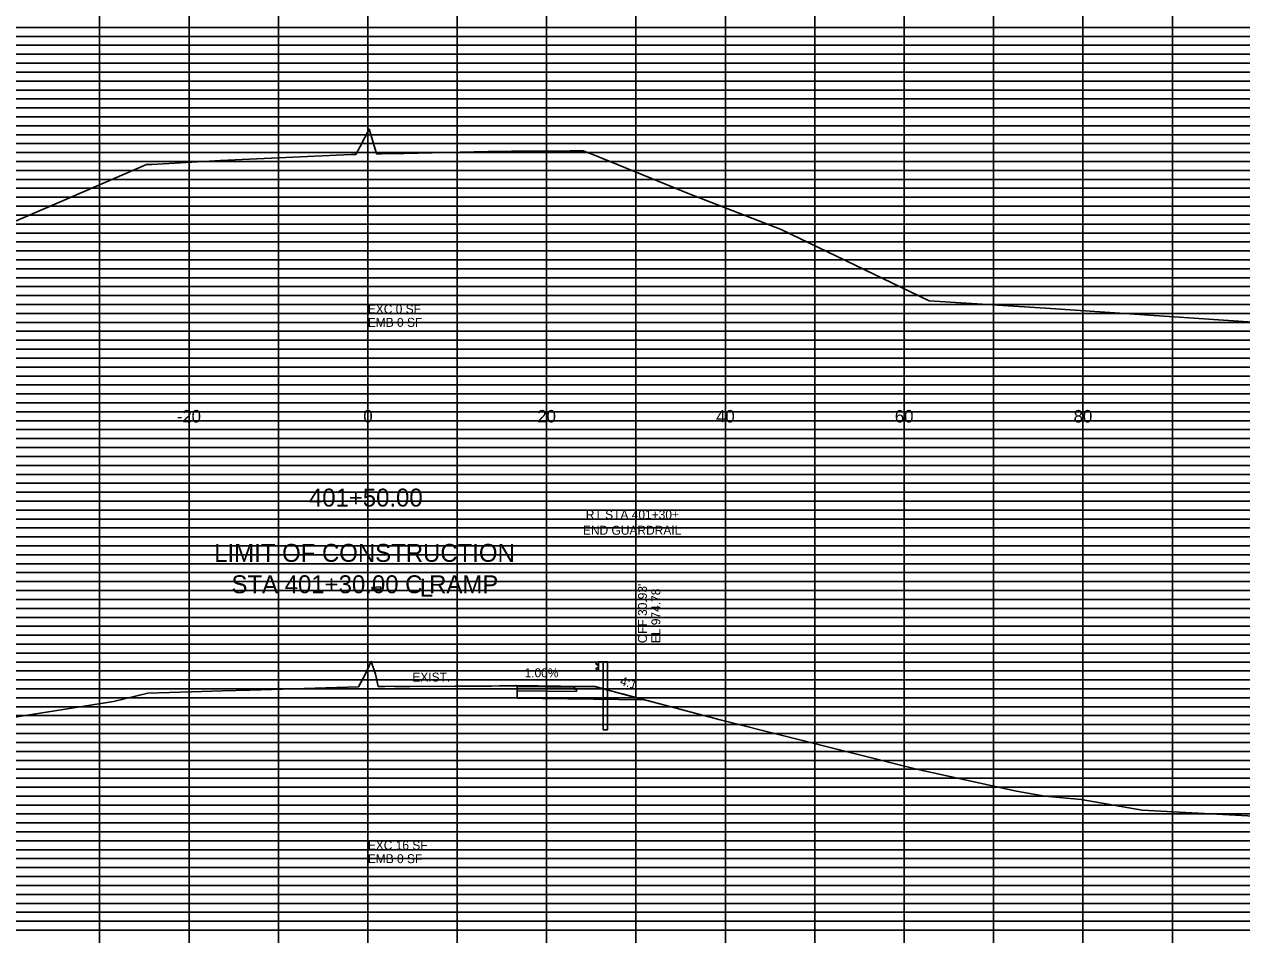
# Model space of a CAD drawing. Extents: x 2313580 to 2322968, y 282099 to 303247.
# Drawn here: x 2315420.5 to 2315556.6, y 285194.6 to 285296.5 of the extents above; entities that cross this region are included whole.
import ezdxf

# ---------------------------------------------------------------- set-up
doc = ezdxf.new("R2010")
doc.units = 0
for name, color, linetype in [('DESIGN - CENTERLINE - Proposed', 7, 'Continuous'), ('DESIGN - DRAINAGE - Text', 7, 'Continuous'), ('DESIGN - EARTHWORK - Excavation Limit Lines', 7, 'Continuous'), ('DESIGN - ROW - Right-of-Way Linework', 7, 'Continuous'), ('DESIGN - SCRATCH - User 1', 7, 'Continuous'), ('DESIGN - SHEET - Light Grid', 7, 'Continuous'), ('DESIGN - SHEET - Linework', 7, 'Continuous'), ('DESIGN - TRANSPORTATION - Text', 7, 'Continuous'), ('DESIGN - TYPICAL - Finished Grade and Subgrade', 7, 'Continuous'), ('DESIGN - TYPICAL - Finished Grade Slopes Text', 7, 'Continuous'), ('DESIGN - TYPICAL - Guardrail', 7, 'Continuous'), ('DESIGN - TYPICAL - Text', 7, 'Continuous'), ('Scratch Level', 7, 'Continuous'), ('SURVEY - GROUND - Top of Ground', 7, 'Continuous')]:
    doc.layers.add(name, color=color, linetype=linetype)

# ---------------------------------------------------------------- blocks, each defined once
blk = doc.blocks.new('GRTYP')
at = {"layer": 'DESIGN - CENTERLINE - Proposed'}
for p, q in [((0.162, 0.37), (0.162, 0.37)), ((0.162, 0.37), (0.162, 0.37)), ((0.264, 0.37), (0.264, 0.37)), ((0.264, 0.37), (0.264, 0.37))]:
    blk.add_line(p, q, dxfattribs=at)
for points in [[(0.059, 0.567), (0.04, 0.563), (0.004, 0.539), (0, 0.531), (0.004, 0.523), (0.055, 0.492), (0.059, 0.484), (0.059, 0.464), (0.055, 0.456), (0.004, 0.425), (0, 0.417), (0.004, 0.409), (0.04, 0.385), (0.059, 0.382)], [(0.162, 0.374), (0.059, 0.374), (0.059, 0.574), (0.162, 0.574)], [(0.264, -0.126), (0.264, 0.574), (0.162, 0.574), (0.162, -0.075)], [(0.162, -0.075), (0.162, -0.949), (0.264, -0.949), (0.264, -0.122)]]:
    blk.add_lwpolyline(points, dxfattribs=at)

msp = doc.modelspace()

# ---------------------------------------------------------------- linework, layer by layer
at = {"layer": 'DESIGN - ROW - Right-of-Way Linework'}
msp.add_lwpolyline([(2315461.92, 285222.39), (2315463.25, 285222.39), (2315463.6, 285222.4), (2315473.62, 285222.47), (2315475.6, 285222.48), (2315484.39, 285222.37), (2315484.39, 285222.37), (2315485.73, 285222), (2315487.39, 285221.56), (2315489.81, 285220.9), (2315489.81, 285220.9)], dxfattribs=at)
at = {"layer": 'DESIGN - SCRATCH - User 1'}
msp.add_lwpolyline([(2315460.35, 285233.53), (2315460.35, 285233.33), (2315459.35, 285233.27), (2315459.35, 285233.48)], close=True, dxfattribs=at)
msp.add_lwpolyline([(2315460.35, 285233.53), (2315460.35, 285233.33), (2315459.35, 285233.27), (2315459.35, 285233.48)], close=True, dxfattribs=at)
msp.add_lwpolyline([(2315460.35, 285233.53), (2315460.35, 285233.33), (2315459.35, 285233.27), (2315459.35, 285233.48)], close=True, dxfattribs=at)
msp.add_lwpolyline([(2315460.35, 285233.53), (2315460.35, 285233.33), (2315459.35, 285233.27), (2315459.35, 285233.48)], close=True, dxfattribs=at)
at = {"layer": 'DESIGN - SHEET - Light Grid'}
for p, q in [((2315378.88, 285295.13), (2315458.88, 285295.13)), ((2315458.88, 285295.13), (2315538.88, 285295.13)), ((2315538.88, 285295.13), (2315618.88, 285295.13)), ((2315378.88, 285294.13), (2315458.88, 285294.13)), ((2315378.88, 285293.13), (2315458.88, 285293.13)), ((2315458.88, 285294.13), (2315538.88, 285294.13)), ((2315458.88, 285293.13), (2315538.88, 285293.13)), ((2315538.88, 285294.13), (2315618.88, 285294.13)), ((2315538.88, 285293.13), (2315618.88, 285293.13)), ((2315378.88, 285292.13), (2315458.88, 285292.13)), ((2315458.88, 285292.13), (2315538.88, 285292.13)), ((2315538.88, 285292.13), (2315618.88, 285292.13)), ((2315378.88, 285291.13), (2315458.88, 285291.13)), ((2315378.88, 285290.13), (2315458.88, 285290.13)), ((2315458.88, 285291.13), (2315538.88, 285291.13)), ((2315458.88, 285290.13), (2315538.88, 285290.13)), ((2315538.88, 285291.13), (2315618.88, 285291.13)), ((2315538.88, 285290.13), (2315618.88, 285290.13)), ((2315378.88, 285289.13), (2315458.88, 285289.13)), ((2315458.88, 285289.13), (2315538.88, 285289.13)), ((2315538.88, 285289.13), (2315618.88, 285289.13)), ((2315378.88, 285288.13), (2315458.88, 285288.13)), ((2315458.88, 285288.13), (2315538.88, 285288.13)), ((2315538.88, 285288.13), (2315618.88, 285288.13)), ((2315378.88, 285287.13), (2315458.88, 285287.13)), ((2315458.88, 285287.13), (2315538.88, 285287.13)), ((2315538.88, 285287.13), (2315618.88, 285287.13)), ((2315378.88, 285285.13), (2315458.88, 285285.13)), ((2315458.88, 285285.13), (2315538.88, 285285.13)), ((2315538.88, 285285.13), (2315618.88, 285285.13)), ((2315378.88, 285284.13), (2315458.88, 285284.13)), ((2315458.88, 285284.13), (2315538.88, 285284.13)), ((2315538.88, 285284.13), (2315618.88, 285284.13)), ((2315378.88, 285283.13), (2315458.88, 285283.13)), ((2315378.88, 285282.13), (2315458.88, 285282.13)), ((2315458.88, 285283.13), (2315538.88, 285283.13)), ((2315458.88, 285282.13), (2315538.88, 285282.13)), ((2315538.88, 285283.13), (2315618.88, 285283.13)), ((2315538.88, 285282.13), (2315618.88, 285282.13)), ((2315378.88, 285281.13), (2315458.88, 285281.13)), ((2315458.88, 285281.13), (2315538.88, 285281.13)), ((2315538.88, 285281.13), (2315618.88, 285281.13)), ((2315378.88, 285280.13), (2315458.88, 285280.13)), ((2315458.88, 285280.13), (2315538.88, 285280.13)), ((2315538.88, 285280.13), (2315618.88, 285280.13)), ((2315378.88, 285279.13), (2315458.88, 285279.13)), ((2315378.88, 285278.13), (2315458.88, 285278.13)), ((2315458.88, 285279.13), (2315538.88, 285279.13)), ((2315458.88, 285278.13), (2315538.88, 285278.13)), ((2315538.88, 285279.13), (2315618.88, 285279.13)), ((2315538.88, 285278.13), (2315618.88, 285278.13)), ((2315378.88, 285277.13), (2315458.88, 285277.13)), ((2315458.88, 285277.13), (2315538.88, 285277.13)), ((2315538.88, 285277.13), (2315618.88, 285277.13)), ((2315378.88, 285275.13), (2315458.88, 285275.13)), ((2315458.88, 285275.13), (2315538.88, 285275.13)), ((2315538.88, 285275.13), (2315618.88, 285275.13)), ((2315378.88, 285274.13), (2315458.88, 285274.13)), ((2315458.88, 285274.13), (2315538.88, 285274.13)), ((2315538.88, 285274.13), (2315618.88, 285274.13)), ((2315378.88, 285273.13), (2315458.88, 285273.13)), ((2315458.88, 285273.13), (2315538.88, 285273.13)), ((2315538.88, 285273.13), (2315618.88, 285273.13)), ((2315378.88, 285272.13), (2315458.88, 285272.13)), ((2315378.88, 285271.13), (2315458.88, 285271.13)), ((2315458.88, 285272.13), (2315538.88, 285272.13)), ((2315458.88, 285271.13), (2315538.88, 285271.13)), ((2315538.88, 285272.13), (2315618.88, 285272.13)), ((2315538.88, 285271.13), (2315618.88, 285271.13)), ((2315378.88, 285270.13), (2315458.88, 285270.13)), ((2315458.88, 285270.13), (2315538.88, 285270.13)), ((2315538.88, 285270.13), (2315618.88, 285270.13)), ((2315378.88, 285269.13), (2315458.88, 285269.13)), ((2315458.88, 285269.13), (2315538.88, 285269.13)), ((2315538.88, 285269.13), (2315618.88, 285269.13)), ((2315378.88, 285268.13), (2315458.88, 285268.13)), ((2315378.88, 285267.13), (2315458.88, 285267.13)), ((2315458.88, 285268.13), (2315538.88, 285268.13)), ((2315458.88, 285267.13), (2315538.88, 285267.13)), ((2315538.88, 285268.13), (2315618.88, 285268.13)), ((2315538.88, 285267.13), (2315618.88, 285267.13)), ((2315378.88, 285265.13), (2315458.88, 285265.13)), ((2315458.88, 285265.13), (2315538.88, 285265.13)), ((2315538.88, 285265.13), (2315618.88, 285265.13)), ((2315378.88, 285264.13), (2315458.88, 285264.13)), ((2315378.88, 285263.13), (2315458.88, 285263.13)), ((2315458.88, 285264.13), (2315538.88, 285264.13)), ((2315458.88, 285263.13), (2315538.88, 285263.13)), ((2315538.88, 285264.13), (2315618.88, 285264.13)), ((2315538.88, 285263.13), (2315618.88, 285263.13)), ((2315378.88, 285262.13), (2315458.88, 285262.13)), ((2315458.88, 285262.13), (2315538.88, 285262.13)), ((2315538.88, 285262.13), (2315618.88, 285262.13)), ((2315378.88, 285261.13), (2315458.88, 285261.13)), ((2315458.88, 285261.13), (2315538.88, 285261.13)), ((2315538.88, 285261.13), (2315618.88, 285261.13)), ((2315378.88, 285260.13), (2315458.88, 285260.13)), ((2315378.88, 285259.13), (2315458.88, 285259.13)), ((2315458.88, 285260.13), (2315538.88, 285260.13)), ((2315458.88, 285259.13), (2315538.88, 285259.13)), ((2315538.88, 285260.13), (2315618.88, 285260.13)), ((2315538.88, 285259.13), (2315618.88, 285259.13)), ((2315378.88, 285258.13), (2315458.88, 285258.13)), ((2315458.88, 285258.13), (2315538.88, 285258.13)), ((2315538.88, 285258.13), (2315618.88, 285258.13)), ((2315378.88, 285257.13), (2315458.88, 285257.13)), ((2315458.88, 285257.13), (2315538.88, 285257.13)), ((2315538.88, 285257.13), (2315618.88, 285257.13)), ((2315378.88, 285255.13), (2315458.88, 285255.13)), ((2315458.88, 285255.13), (2315538.88, 285255.13)), ((2315538.88, 285255.13), (2315618.88, 285255.13)), ((2315378.88, 285254.13), (2315458.88, 285254.13)), ((2315458.88, 285254.13), (2315538.88, 285254.13)), ((2315538.88, 285254.13), (2315618.88, 285254.13)), ((2315378.88, 285253.13), (2315458.88, 285253.13)), ((2315378.88, 285252.13), (2315458.88, 285252.13)), ((2315458.88, 285253.13), (2315538.88, 285253.13)), ((2315458.88, 285252.13), (2315538.88, 285252.13)), ((2315538.88, 285253.13), (2315618.88, 285253.13)), ((2315538.88, 285252.13), (2315618.88, 285252.13)), ((2315378.88, 285251.13), (2315458.88, 285251.13)), ((2315458.88, 285251.13), (2315538.88, 285251.13)), ((2315538.88, 285251.13), (2315618.88, 285251.13)), ((2315378.88, 285250.13), (2315458.88, 285250.13)), ((2315458.88, 285250.13), (2315538.88, 285250.13)), ((2315538.88, 285250.13), (2315618.88, 285250.13)), ((2315378.88, 285249.13), (2315458.88, 285249.13)), ((2315378.88, 285248.13), (2315458.88, 285248.13)), ((2315458.88, 285249.13), (2315538.88, 285249.13)), ((2315458.88, 285248.13), (2315538.88, 285248.13)), ((2315538.88, 285249.13), (2315618.88, 285249.13)), ((2315538.88, 285248.13), (2315618.88, 285248.13)), ((2315378.88, 285247.13), (2315458.88, 285247.13)), ((2315458.88, 285247.13), (2315538.88, 285247.13)), ((2315538.88, 285247.13), (2315618.88, 285247.13)), ((2315378.88, 285245.13), (2315458.88, 285245.13)), ((2315378.88, 285244.13), (2315458.88, 285244.13)), ((2315458.88, 285245.13), (2315538.88, 285245.13)), ((2315458.88, 285244.13), (2315538.88, 285244.13)), ((2315538.88, 285245.13), (2315618.88, 285245.13)), ((2315538.88, 285244.13), (2315618.88, 285244.13)), ((2315378.88, 285243.13), (2315458.88, 285243.13)), ((2315458.88, 285243.13), (2315538.88, 285243.13)), ((2315538.88, 285243.13), (2315618.88, 285243.13)), ((2315378.88, 285242.13), (2315458.88, 285242.13)), ((2315378.88, 285241.13), (2315458.88, 285241.13)), ((2315458.88, 285242.13), (2315538.88, 285242.13)), ((2315458.88, 285241.13), (2315538.88, 285241.13)), ((2315538.88, 285242.13), (2315618.88, 285242.13)), ((2315538.88, 285241.13), (2315618.88, 285241.13)), ((2315378.88, 285240.13), (2315458.88, 285240.13)), ((2315458.88, 285240.13), (2315538.88, 285240.13)), ((2315538.88, 285240.13), (2315618.88, 285240.13)), ((2315378.88, 285239.13), (2315458.88, 285239.13)), ((2315458.88, 285239.13), (2315538.88, 285239.13)), ((2315538.88, 285239.13), (2315618.88, 285239.13)), ((2315378.88, 285238.13), (2315458.88, 285238.13)), ((2315378.88, 285237.13), (2315458.88, 285237.13)), ((2315458.88, 285238.13), (2315538.88, 285238.13)), ((2315458.88, 285237.13), (2315538.88, 285237.13)), ((2315538.88, 285238.13), (2315618.88, 285238.13)), ((2315538.88, 285237.13), (2315618.88, 285237.13)), ((2315378.88, 285235.13), (2315458.88, 285235.13)), ((2315458.88, 285235.13), (2315538.88, 285235.13)), ((2315538.88, 285235.13), (2315618.88, 285235.13)), ((2315378.88, 285234.13), (2315458.88, 285234.13)), ((2315378.88, 285233.13), (2315458.88, 285233.13)), ((2315458.88, 285234.13), (2315538.88, 285234.13)), ((2315458.88, 285233.13), (2315538.88, 285233.13)), ((2315538.88, 285234.13), (2315618.88, 285234.13)), ((2315538.88, 285233.13), (2315618.88, 285233.13)), ((2315378.88, 285232.13), (2315458.88, 285232.13)), ((2315458.88, 285232.13), (2315538.88, 285232.13)), ((2315538.88, 285232.13), (2315618.88, 285232.13)), ((2315378.88, 285231.13), (2315458.88, 285231.13)), ((2315458.88, 285231.13), (2315538.88, 285231.13)), ((2315538.88, 285231.13), (2315618.88, 285231.13)), ((2315378.88, 285230.13), (2315458.88, 285230.13)), ((2315378.88, 285229.13), (2315458.88, 285229.13)), ((2315458.88, 285230.13), (2315538.88, 285230.13)), ((2315458.88, 285229.13), (2315538.88, 285229.13)), ((2315538.88, 285230.13), (2315618.88, 285230.13)), ((2315538.88, 285229.13), (2315618.88, 285229.13)), ((2315378.88, 285228.13), (2315458.88, 285228.13)), ((2315458.88, 285228.13), (2315538.88, 285228.13)), ((2315538.88, 285228.13), (2315618.88, 285228.13)), ((2315378.88, 285227.13), (2315458.88, 285227.13)), ((2315458.88, 285227.13), (2315538.88, 285227.13)), ((2315538.88, 285227.13), (2315618.88, 285227.13)), ((2315378.88, 285225.13), (2315458.88, 285225.13)), ((2315458.88, 285225.13), (2315538.88, 285225.13)), ((2315538.88, 285225.13), (2315618.88, 285225.13)), ((2315378.88, 285224.13), (2315458.88, 285224.13)), ((2315458.88, 285224.13), (2315538.88, 285224.13)), ((2315538.88, 285224.13), (2315618.88, 285224.13)), ((2315378.88, 285223.13), (2315458.88, 285223.13)), ((2315378.88, 285222.13), (2315458.88, 285222.13)), ((2315458.88, 285223.13), (2315538.88, 285223.13)), ((2315458.88, 285222.13), (2315538.88, 285222.13)), ((2315538.88, 285223.13), (2315618.88, 285223.13)), ((2315538.88, 285222.13), (2315618.88, 285222.13)), ((2315378.88, 285221.13), (2315458.88, 285221.13)), ((2315458.88, 285221.13), (2315538.88, 285221.13)), ((2315538.88, 285221.13), (2315618.88, 285221.13)), ((2315378.88, 285220.13), (2315458.88, 285220.13)), ((2315458.88, 285220.13), (2315538.88, 285220.13)), ((2315538.88, 285220.13), (2315618.88, 285220.13)), ((2315378.88, 285219.13), (2315458.88, 285219.13)), ((2315378.88, 285218.13), (2315458.88, 285218.13)), ((2315458.88, 285219.13), (2315538.88, 285219.13)), ((2315458.88, 285218.13), (2315538.88, 285218.13)), ((2315538.88, 285219.13), (2315618.88, 285219.13)), ((2315538.88, 285218.13), (2315618.88, 285218.13)), ((2315378.88, 285217.13), (2315458.88, 285217.13)), ((2315458.88, 285217.13), (2315538.88, 285217.13)), ((2315538.88, 285217.13), (2315618.88, 285217.13)), ((2315378.88, 285215.13), (2315458.88, 285215.13)), ((2315378.88, 285214.13), (2315458.88, 285214.13)), ((2315458.88, 285215.13), (2315538.88, 285215.13)), ((2315458.88, 285214.13), (2315538.88, 285214.13)), ((2315538.88, 285215.13), (2315618.88, 285215.13)), ((2315538.88, 285214.13), (2315618.88, 285214.13)), ((2315378.88, 285213.13), (2315458.88, 285213.13)), ((2315458.88, 285213.13), (2315538.88, 285213.13)), ((2315538.88, 285213.13), (2315618.88, 285213.13)), ((2315378.88, 285212.13), (2315458.88, 285212.13)), ((2315378.88, 285211.13), (2315458.88, 285211.13)), ((2315458.88, 285212.13), (2315538.88, 285212.13)), ((2315458.88, 285211.13), (2315538.88, 285211.13)), ((2315538.88, 285212.13), (2315618.88, 285212.13)), ((2315538.88, 285211.13), (2315618.88, 285211.13)), ((2315378.88, 285210.13), (2315458.88, 285210.13)), ((2315458.88, 285210.13), (2315538.88, 285210.13)), ((2315538.88, 285210.13), (2315618.88, 285210.13)), ((2315378.88, 285209.13), (2315458.88, 285209.13)), ((2315458.88, 285209.13), (2315538.88, 285209.13)), ((2315538.88, 285209.13), (2315618.88, 285209.13)), ((2315378.88, 285208.13), (2315458.88, 285208.13)), ((2315378.88, 285207.13), (2315458.88, 285207.13)), ((2315458.88, 285208.13), (2315538.88, 285208.13)), ((2315458.88, 285207.13), (2315538.88, 285207.13)), ((2315538.88, 285208.13), (2315618.88, 285208.13)), ((2315538.88, 285207.13), (2315618.88, 285207.13)), ((2315378.88, 285205.13), (2315458.88, 285205.13)), ((2315458.88, 285205.13), (2315538.88, 285205.13)), ((2315538.88, 285205.13), (2315618.88, 285205.13)), ((2315378.88, 285204.13), (2315458.88, 285204.13)), ((2315378.88, 285203.13), (2315458.88, 285203.13)), ((2315458.88, 285204.13), (2315538.88, 285204.13)), ((2315458.88, 285203.13), (2315538.88, 285203.13)), ((2315538.88, 285204.13), (2315618.88, 285204.13)), ((2315538.88, 285203.13), (2315618.88, 285203.13)), ((2315378.88, 285202.13), (2315458.88, 285202.13)), ((2315458.88, 285202.13), (2315538.88, 285202.13)), ((2315538.88, 285202.13), (2315618.88, 285202.13)), ((2315378.88, 285201.13), (2315458.88, 285201.13)), ((2315458.88, 285201.13), (2315538.88, 285201.13)), ((2315538.88, 285201.13), (2315618.88, 285201.13)), ((2315378.88, 285200.13), (2315458.88, 285200.13)), ((2315378.88, 285199.13), (2315458.88, 285199.13)), ((2315458.88, 285200.13), (2315538.88, 285200.13)), ((2315458.88, 285199.13), (2315538.88, 285199.13)), ((2315538.88, 285200.13), (2315618.88, 285200.13)), ((2315538.88, 285199.13), (2315618.88, 285199.13)), ((2315378.88, 285198.13), (2315458.88, 285198.13)), ((2315458.88, 285198.13), (2315538.88, 285198.13)), ((2315538.88, 285198.13), (2315618.88, 285198.13)), ((2315378.88, 285197.13), (2315458.88, 285197.13)), ((2315458.88, 285197.13), (2315538.88, 285197.13)), ((2315538.88, 285197.13), (2315618.88, 285197.13)), ((2315378.88, 285195.13), (2315458.88, 285195.13)), ((2315458.88, 285195.13), (2315538.88, 285195.13)), ((2315538.88, 285195.13), (2315618.88, 285195.13))]:
    msp.add_line(p, q, dxfattribs=at)
at = {"layer": 'DESIGN - SHEET - Linework'}
for p, q in [((2315428.88, 285096.13), (2315428.88, 285306.13)), ((2315438.88, 285096.13), (2315438.88, 285306.13)), ((2315448.88, 285096.13), (2315448.88, 285306.13)), ((2315458.88, 285096.13), (2315458.88, 285306.13)), ((2315468.88, 285096.13), (2315468.88, 285306.13)), ((2315478.88, 285096.13), (2315478.88, 285306.13)), ((2315488.88, 285096.13), (2315488.88, 285306.13)), ((2315498.88, 285096.13), (2315498.88, 285306.13)), ((2315508.88, 285096.13), (2315508.88, 285306.13)), ((2315518.88, 285096.13), (2315518.88, 285306.13)), ((2315528.88, 285096.13), (2315528.88, 285306.13)), ((2315538.88, 285096.13), (2315538.88, 285306.13)), ((2315548.88, 285096.13), (2315548.88, 285306.13)), ((2315298.88, 285296.13), (2315578.88, 285296.13)), ((2315298.88, 285286.13), (2315618.88, 285286.13)), ((2315298.88, 285276.13), (2315618.88, 285276.13)), ((2315298.88, 285266.13), (2315618.88, 285266.13)), ((2315298.88, 285256.13), (2315618.88, 285256.13)), ((2315308.88, 285256.13), (2315608.88, 285256.13)), ((2315298.88, 285246.13), (2315618.88, 285246.13)), ((2315298.88, 285236.13), (2315618.88, 285236.13)), ((2315298.88, 285226.13), (2315618.88, 285226.13)), ((2315298.88, 285216.13), (2315618.88, 285216.13)), ((2315298.88, 285206.13), (2315618.88, 285206.13)), ((2315298.88, 285196.13), (2315618.88, 285196.13)), ((2315308.88, 285196.13), (2315608.88, 285196.13))]:
    msp.add_line(p, q, dxfattribs=at)
at = {"layer": 'DESIGN - TYPICAL - Finished Grade and Subgrade'}
for points in [[(2315475.6, 285222.48), (2315481.91, 285222.4), (2315481.91, 285222.3), (2315475.6, 285222.38)], [(2315475.6, 285221.92), (2315482.22, 285221.84), (2315482.22, 285222.09), (2315482.01, 285222.1), (2315482.01, 285222.3), (2315481.91, 285222.3), (2315481.91, 285222.4), (2315484.39, 285222.37), (2315489.81, 285220.9), (2315475.6, 285221.09)], [(2315475.6, 285222.38), (2315482.01, 285222.3), (2315482.01, 285222.1), (2315475.6, 285222.17)], [(2315475.6, 285222.17), (2315482.22, 285222.09), (2315482.22, 285221.84), (2315475.6, 285221.92)]]:
    msp.add_lwpolyline(points, close=True, dxfattribs=at)
at = {"layer": 'Scratch Level'}
for points in [[(2315462.07, 285222.39), (2315472.71, 285222.42), (2315475.22, 285222.45), (2315475.29, 285222.48), (2315473.62, 285222.47), (2315463.6, 285222.4), (2315463.25, 285222.39)], [(2315475.29, 285222.48), (2315475.4, 285222.52), (2315482.98, 285222.41), (2315484.3, 285222.4), (2315485.78, 285221.97), (2315489.81, 285220.9), (2315475.6, 285221.09), (2315475.6, 285221.92), (2315475.6, 285222.17), (2315475.6, 285222.38), (2315475.6, 285222.48)]]:
    msp.add_lwpolyline(points, close=True, dxfattribs=at)
at = {"layer": 'SURVEY - GROUND - Top of Ground'}
for points in [[(2315415.71, 285272.85), (2315424.67, 285276.7), (2315434.11, 285280.78), (2315434.72, 285280.81), (2315442.42, 285281.25), (2315457.02, 285281.9), (2315457.53, 285281.92), (2315458.02, 285282.8), (2315459.03, 285284.75), (2315459.85, 285282.02), (2315459.86, 285281.98), (2315460.43, 285281.99), (2315462.94, 285282.04), (2315472.34, 285282.25), (2315474.97, 285282.3), (2315474.99, 285282.29), (2315481.53, 285282.32), (2315482.97, 285282.32), (2315484.25, 285281.84), (2315494.84, 285277.51), (2315505.11, 285273.54), (2315521.69, 285265.53), (2315534.69, 285264.74), (2315582.27, 285261.53)], [(2315419.17, 285218.91), (2315430.44, 285220.72), (2315434.28, 285221.66), (2315439.12, 285221.81), (2315442.6, 285221.91), (2315445.69, 285221.98), (2315457.83, 285222.35), (2315458.58, 285223.74), (2315459.27, 285225.2), (2315459.73, 285223.76), (2315460.05, 285222.38), (2315460.79, 285222.38), (2315472.71, 285222.42), (2315475.22, 285222.45), (2315475.4, 285222.52), (2315482.98, 285222.41), (2315484.3, 285222.4), (2315485.78, 285221.97), (2315498.31, 285218.65), (2315520.27, 285213.13), (2315531.45, 285210.67), (2315534.61, 285210.12), (2315538.69, 285209.75), (2315545.5, 285208.56), (2315575.41, 285206.96)]]:
    msp.add_lwpolyline(points, dxfattribs=at)

# ---------------------------------------------------------------- block references
at = {"layer": 'DESIGN - TYPICAL - Guardrail', "xscale": 5, "yscale": 5}
msp.add_blockref('GRTYP', (2315484.39, 285222.29), dxfattribs=at)

# ---------------------------------------------------------------- texts
at = {"layer": 'DESIGN - DRAINAGE - Text'}
for s, p in [("OFF 30.93'", (2315490.1, 285227.24)), ('EL 974.78', (2315491.6, 285227.24))]:
    msp.add_text(s, height=1.001, rotation=90, dxfattribs=at).set_placement(p)
at = {"layer": 'DESIGN - EARTHWORK - Excavation Limit Lines'}
for s, p in [('EXC 0 SF', (2315458.88, 285264.13)), ('EMB 0 SF', (2315458.88, 285262.63)), ('EXC 16 SF', (2315458.88, 285204.13)), ('EMB 0 SF', (2315458.88, 285202.63))]:
    msp.add_text(s, height=1, dxfattribs=at).set_placement(p)
at = {"layer": 'DESIGN - TRANSPORTATION - Text'}
for s, p in [('RT STA 401+30%%P', (2315483.27, 285241.12)), ('END GUARDRAIL', (2315482.94, 285239.37))]:
    msp.add_text(s, height=1.0015, dxfattribs=at).set_placement(p)
at = {"layer": 'DESIGN - TYPICAL - Finished Grade Slopes Text'}
for s, rotation, p in [('EXIST.', 359.9547, (2315463.86, 285222.95)), ('1.00%', 359.9547, (2315476.42, 285223.43)), ('4:1', 344.1584, (2315487.02, 285222.58))]:
    msp.add_text(s, height=1, rotation=rotation, dxfattribs=at).set_placement(p)
at = {"layer": 'DESIGN - TYPICAL - Text'}
for s, height, p in [('-20', 1.4, (2315437.51, 285251.93)), ('0', 1.4, (2315458.38, 285251.93)), ('20', 1.4, (2315477.84, 285251.93)), ('40', 1.4, (2315497.84, 285251.93)), ('60', 1.4, (2315517.84, 285251.93)), ('80', 1.4, (2315537.84, 285251.93)), ('401+50.00', 2, (2315452.3, 285242.53)), ('LIMIT OF CONSTRUCTION', 2.0029, (2315441.7, 285236.34)), ('STA 401+30.00 C RAMP', 2.0029, (2315443.63, 285232.83)), ('L', 2, (2315464.69, 285232.44))]:
    msp.add_text(s, height=height, dxfattribs=at).set_placement(p)

doc.saveas('drawing.dxf')
